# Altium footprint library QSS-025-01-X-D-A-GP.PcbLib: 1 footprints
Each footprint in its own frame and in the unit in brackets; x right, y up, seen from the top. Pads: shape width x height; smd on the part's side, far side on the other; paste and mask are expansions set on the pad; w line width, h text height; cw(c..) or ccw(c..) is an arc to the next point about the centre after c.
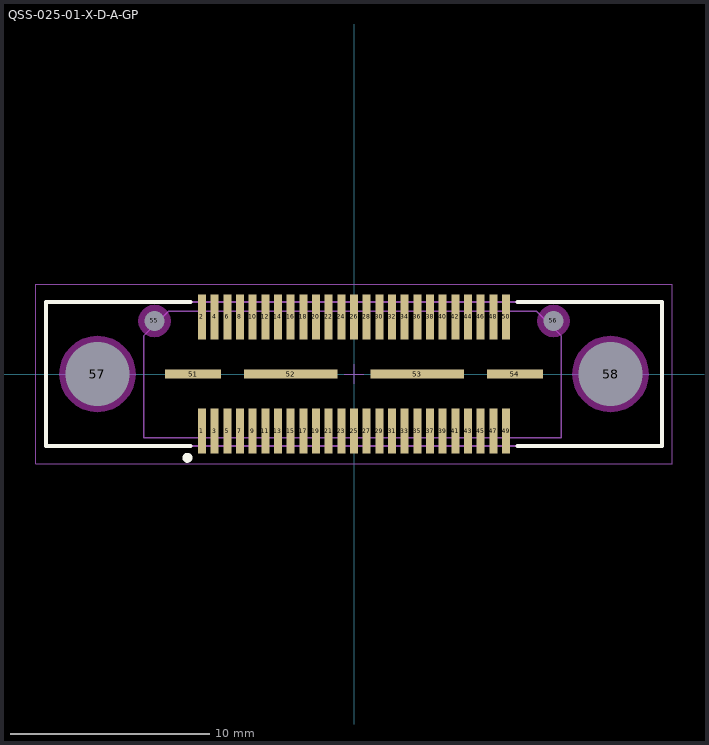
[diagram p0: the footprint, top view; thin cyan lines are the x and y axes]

## QSS-025-01-X-D-A-GP [mm] "0.635mm pitch, 50 pin, high speed socket; w/alignment pins"
height 3.63
pads (58):
  rect 0.4x2.25 smd mask+0: 1(-7.62,-2.865) 2(-7.62,2.865) 3(-6.985,-2.865) 4(-6.985,2.865) 5(-6.35,-2.865) 6(-6.35,2.865) 7(-5.715,-2.865) 8(-5.715,2.865) 9(-5.08,-2.865) 10(-5.08,2.865) 11(-4.445,-2.865) 12(-4.445,2.865) 13(-3.81,-2.865) 14(-3.81,2.865) 15(-3.175,-2.865) 16(-3.175,2.865) 17(-2.54,-2.865) 18(-2.54,2.865) 19(-1.905,-2.865) 20(-1.905,2.865) 21(-1.27,-2.865) 22(-1.27,2.865) 23(-0.635,-2.865) 24(-0.635,2.865) 25(0,-2.865) 26(0,2.865) 27(0.635,-2.865) 28(0.635,2.865) 29(1.27,-2.865) 30(1.27,2.865) 31(1.905,-2.865) 32(1.905,2.865) 33(2.54,-2.865) 34(2.54,2.865) 35(3.175,-2.865) 36(3.175,2.865) 37(3.81,-2.865) 38(3.81,2.865) 39(4.445,-2.865) 40(4.445,2.865) 41(5.08,-2.865) 42(5.08,2.865) 43(5.715,-2.865) 44(5.715,2.865) 45(6.35,-2.865) 46(6.35,2.865) 47(6.985,-2.865) 48(6.985,2.865) 49(7.62,-2.865) 50(7.62,2.865)
  rect 2.8x0.45 smd mask+0: 51(-8.064,0) 54(8.064,0)
  rect 4.7x0.45 smd mask+0: 52(-3.175,0) 53(3.175,0)
  round 0.5 hole 1 unplated mask+0: 55(-10.003,2.657) 56(10,2.657)
  round 1 hole 3.2 unplated mask+0: 57(-12.859,0) 58(12.859,0)
Top Overlay:
  circle w0.25: c-8.35,-4.2 r0.125
  lines w0.2: -8.2,-3.6 -15.45,-3.6 -15.45,3.6 -8.2,3.6 ; 8.2,-3.6 15.45,-3.6 15.45,3.6 8.2,3.6
Keep-Out Layer:
  pour cut-out: -9.196,2.657 -9.224,2.866 -9.304,3.06 -9.432,3.228 -9.6,3.356 -9.794,3.436 -10.003,3.464 -10.212,3.436 -10.406,3.356 -10.574,3.228 -10.702,3.06 -10.782,2.866 -10.81,2.657 -10.782,2.448 -10.702,2.254 -10.574,2.086 -10.406,1.958 -10.212,1.878 -10.003,1.85 -9.794,1.878 -9.6,1.958 -9.432,2.086 -9.304,2.254 -9.224,2.448
  pour cut-out: 10.807,2.657 10.779,2.866 10.699,3.06 10.571,3.228 10.403,3.356 10.209,3.436 10,3.464 9.791,3.436 9.597,3.356 9.429,3.228 9.301,3.06 9.221,2.866 9.193,2.657 9.221,2.448 9.301,2.254 9.429,2.086 9.597,1.958 9.791,1.878 10,1.85 10.209,1.878 10.403,1.958 10.571,2.086 10.699,2.254 10.779,2.448
  pour cut-out: -10.95,0 -10.986,0.372 -11.095,0.731 -11.272,1.061 -11.509,1.35 -11.798,1.587 -12.128,1.764 -12.487,1.873 -12.859,1.909 -13.231,1.873 -13.59,1.764 -13.92,1.587 -14.209,1.35 -14.446,1.061 -14.623,0.731 -14.732,0.372 -14.768,0 -14.732,-0.372 -14.623,-0.731 -14.446,-1.061 -14.209,-1.35 -13.92,-1.587 -13.59,-1.764 -13.231,-1.873 -12.859,-1.909 -12.487,-1.873 -12.128,-1.764 -11.798,-1.587 -11.509,-1.35 -11.272,-1.061 -11.095,-0.731 -10.986,-0.372
  pour cut-out: 14.768,0 14.732,0.372 14.623,0.731 14.446,1.061 14.209,1.35 13.92,1.587 13.59,1.764 13.231,1.873 12.859,1.909 12.487,1.873 12.128,1.764 11.798,1.587 11.509,1.35 11.272,1.061 11.095,0.731 10.986,0.372 10.95,0 10.986,-0.372 11.095,-0.731 11.272,-1.061 11.509,-1.35 11.798,-1.587 12.128,-1.764 12.487,-1.873 12.859,-1.909 13.231,-1.873 13.59,-1.764 13.92,-1.587 14.209,-1.35 14.446,-1.061 14.623,-0.731 14.732,-0.372
Mechanical 12:
  lines w0.001: -15.45,-3.6 15.45,-3.6 15.45,3.6 -15.45,3.6 -15.45,-3.6
Mechanical 13:
  lines w0.076: -10.55,-3.2 -10.55,1.905 -9.3,3.15 9.15,3.15 10.4,1.905 10.4,-3.2 -10.55,-3.2
  lines w0.1: -15.45,-3.6 15.45,-3.6 15.45,3.6 -15.45,3.6 -15.45,-3.6
  text ".Designator" at 0.254,0.254 h1.52
Mechanical 15:
  lines w0.05: -0.5,0 0.5,0 ; 0,-0.5 0,0.5 ; -15.95,-4.5 15.95,-4.5 15.95,4.5 -15.95,4.5 -15.95,-4.5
